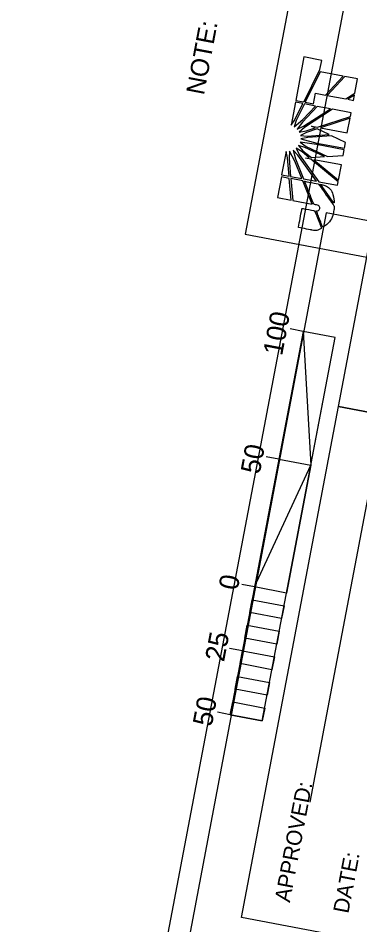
# Model space of a CAD drawing. Extents: x 1615642 to 1617075, y 899305 to 901510.
# Drawn here: x 1616717.4 to 1616848.8, y 900421.5 to 900770.1 of the extents above; entities that cross this region are included whole.
import ezdxf

# ---------------------------------------------------------------- set-up
doc = ezdxf.new("R2010")
doc.units = 0
for name, color, linetype in [('Default', 7, 'Continuous'), ('DEV BORDER CELL', 7, 'Continuous'), ('Prop DSN Text', 7, 'Continuous'), ('Scratch_Level_0', 7, 'Continuous'), ('Sheet Clip Boundary CELL', 7, 'Continuous'), ('Sheet Data Field CELL', 7, 'Continuous'), ('Sheet Plan CELL', 7, 'Continuous'), ('Sheet Title CELL', 7, 'Continuous')]:
    doc.layers.add(name, color=color, linetype=linetype)

msp = doc.modelspace()

# ---------------------------------------------------------------- linework, layer by layer
at = {"layer": 'Default'}
for p, q in [((1616827.31, 900755.17), (1616824.15, 900738.45)), ((1616834.16, 900753.88), (1616827.31, 900755.17)), ((1616833.49, 900750.32), (1616834.16, 900753.88)), ((1616827.31, 900737.85), (1616833.49, 900750.32)), ((1616833.63, 900749.42), (1616827.78, 900737.76)), ((1616842.41, 900747.76), (1616833.63, 900749.42)), ((1616835.63, 900740.51), (1616842.41, 900747.76)), ((1616843.03, 900747.65), (1616836.29, 900740.38)), ((1616847.97, 900746.71), (1616843.03, 900747.65)), ((1616846.95, 900741.32), (1616847.97, 900746.71)), ((1616831.04, 900737.15), (1616831.81, 900741.23)), ((1616831.81, 900741.23), (1616835.63, 900740.51)), ((1616836.29, 900740.38), (1616843.4, 900739.04)), ((1616843.4, 900739.04), (1616846.95, 900741.32)), ((1616846.8, 900740.53), (1616844.18, 900738.89)), ((1616844.18, 900738.89), (1616846.41, 900738.47)), ((1616846.41, 900738.47), (1616846.8, 900740.53)), ((1616824.07, 900737.82), (1616822.36, 900729.01)), ((1616823.84, 900731.04), (1616826.93, 900737.28)), ((1616826.93, 900737.28), (1616824.07, 900737.82)), ((1616824.15, 900738.45), (1616827.22, 900737.87)), ((1616827.54, 900737.17), (1616824.37, 900730.71)), ((1616832.45, 900736.19), (1616826.81, 900730.17)), ((1616826.95, 900731.13), (1616831.74, 900736.32)), ((1616827.18, 900728.51), (1616837.54, 900735.22)), ((1616827.22, 900737.87), (1616827.31, 900737.85)), ((1616831.74, 900736.32), (1616827.54, 900737.17)), ((1616827.78, 900737.76), (1616827.84, 900737.75)), ((1616827.84, 900737.75), (1616831.04, 900737.15)), ((1616837.54, 900735.22), (1616832.45, 900736.19)), ((1616838.37, 900735.07), (1616827.5, 900728.08)), ((1616832.52, 900728.14), (1616845.25, 900732.31)), ((1616845.51, 900733.72), (1616838.37, 900735.07)), ((1616845.25, 900732.31), (1616845.51, 900733.72)), ((1616822.36, 900729.01), (1616823.84, 900731.04)), ((1616823.59, 900728.31), (1616826.95, 900731.13)), ((1616824.37, 900730.71), (1616823.59, 900728.31)), ((1616826.81, 900730.17), (1616824.69, 900727.39)), ((1616824.69, 900727.39), (1616827.18, 900728.51)), ((1616831.69, 900727.87), (1616830.19, 900728.58)), ((1616830.19, 900728.58), (1616832.52, 900728.14)), ((1616845.08, 900731.66), (1616833.66, 900727.92)), ((1616844.01, 900725.97), (1616845.08, 900731.66)), ((1616827.5, 900728.08), (1616825.48, 900726.27)), ((1616825.48, 900726.27), (1616828.21, 900726.76)), ((1616828.28, 900726.16), (1616825.97, 900725.01)), ((1616825.97, 900725.01), (1616828.57, 900724.79)), ((1616828.21, 900726.76), (1616831.69, 900727.87)), ((1616832.4, 900727.52), (1616828.28, 900726.16)), ((1616828.57, 900724.79), (1616836.99, 900725.33)), ((1616837.99, 900724.87), (1616828.83, 900724.24)), ((1616836.99, 900725.33), (1616832.4, 900727.52)), ((1616833.66, 900727.92), (1616844.01, 900725.97)), ((1616843.31, 900722.28), (1616837.99, 900724.87)), ((1616832.18, 900721.51), (1616825.84, 900722.36)), ((1616825.84, 900722.36), (1616828.18, 900720.79)), ((1616828.83, 900724.24), (1616826.09, 900723.67)), ((1616826.09, 900723.67), (1616832.28, 900722.08)), ((1616842.79, 900719.51), (1616832.18, 900721.51)), ((1616832.28, 900722.08), (1616842.89, 900720.07)), ((1616842.89, 900720.07), (1616843.31, 900722.28)), ((1616820.45, 900718.87), (1616818.76, 900709.92)), ((1616821.03, 900716.4), (1616820.45, 900718.87)), ((1616821.82, 900718.94), (1616821.64, 900716.28)), ((1616823.88, 900715.14), (1616821.82, 900718.94)), ((1616825.04, 900717.42), (1616823.18, 900719.36)), ((1616823.18, 900719.36), (1616824.14, 900716.04)), ((1616824.31, 900720.1), (1616825.54, 900717.68)), ((1616826.67, 900718.65), (1616824.31, 900720.1)), ((1616825.24, 900721.11), (1616826.96, 900719.15)), ((1616827.65, 900720.42), (1616825.24, 900721.11)), ((1616829.39, 900716.41), (1616826.67, 900718.65)), ((1616826.96, 900719.15), (1616830.18, 900716.49)), ((1616835.2, 900716.86), (1616827.65, 900720.42)), ((1616828.18, 900720.79), (1616836.35, 900716.92)), ((1616842.37, 900717.33), (1616842.79, 900719.51)), ((1616821.61, 900709.38), (1616821.03, 900716.4)), ((1616821.64, 900716.28), (1616822.22, 900709.27)), ((1616826.53, 900708.45), (1616823.88, 900715.14)), ((1616824.14, 900716.04), (1616827.22, 900708.32)), ((1616832.19, 900707.38), (1616825.04, 900717.42)), ((1616825.54, 900717.68), (1616833.03, 900707.22)), ((1616827.87, 900716.29), (1616829.39, 900716.41)), ((1616829.97, 900715.89), (1616827.87, 900716.29)), ((1616840.5, 900707.17), (1616829.97, 900715.89)), ((1616830.18, 900716.49), (1616835.2, 900716.86)), ((1616841.73, 900713.72), (1616831.12, 900715.68)), ((1616831.12, 900715.68), (1616840.61, 900707.79)), ((1616836.35, 900716.92), (1616842.37, 900717.33)), ((1616840.61, 900707.79), (1616841.73, 900713.72)), ((1616818.64, 900709.09), (1616817.14, 900701.13)), ((1616821.71, 900708.51), (1616818.64, 900709.09)), ((1616818.76, 900709.92), (1616821.61, 900709.38)), ((1616822.41, 900700.13), (1616821.71, 900708.51)), ((1616822.22, 900709.27), (1616826.53, 900708.45)), ((1616826.9, 900707.53), (1616822.29, 900708.4)), ((1616822.29, 900708.4), (1616823.02, 900700.02)), ((1616830.44, 900698.62), (1616826.9, 900707.53)), ((1616827.22, 900708.32), (1616832.19, 900707.38)), ((1616833.03, 900707.22), (1616840.25, 900705.86)), ((1616840.25, 900705.86), (1616840.5, 900707.17)), ((1616817.14, 900701.13), (1616822.41, 900700.13)), ((1616823.02, 900700.02), (1616830.44, 900698.62))]:
    msp.add_line(p, q, dxfattribs=at)
for points in [[(1616827.78, 900737.76), (1616827.84, 900737.75), (1616831.04, 900737.15), (1616831.81, 900741.23), (1616835.63, 900740.51), (1616842.41, 900747.76), (1616833.63, 900749.42), (1616827.78, 900737.76)], [(1616836.29, 900740.38), (1616843.4, 900739.04), (1616846.95, 900741.32), (1616847.97, 900746.71), (1616843.03, 900747.65), (1616836.29, 900740.38), (1616836.29, 900740.38)], [(1616846.41, 900738.47), (1616846.41, 900738.47), (1616846.8, 900740.53), (1616844.18, 900738.89), (1616846.41, 900738.47)], [(1616823.84, 900731.04), (1616826.93, 900737.28), (1616824.07, 900737.82), (1616822.36, 900729.01), (1616823.84, 900731.04)], [(1616823.59, 900728.31), (1616826.95, 900731.13), (1616831.74, 900736.32), (1616827.54, 900737.17), (1616824.37, 900730.71), (1616823.59, 900728.31)], [(1616824.69, 900727.39), (1616827.18, 900728.51), (1616837.54, 900735.22), (1616832.45, 900736.19), (1616826.81, 900730.17), (1616824.69, 900727.39)], [(1616825.48, 900726.27), (1616828.21, 900726.76), (1616831.69, 900727.87), (1616830.19, 900728.58), (1616832.52, 900728.14), (1616845.25, 900732.31), (1616845.51, 900733.72), (1616838.37, 900735.07), (1616827.5, 900728.08), (1616825.48, 900726.27)], [(1616844.01, 900725.97), (1616845.08, 900731.66), (1616833.66, 900727.92), (1616844.01, 900725.97)], [(1616825.97, 900725.01), (1616828.57, 900724.79), (1616836.99, 900725.33), (1616832.4, 900727.52), (1616828.28, 900726.16), (1616825.97, 900725.01)], [(1616826.09, 900723.67), (1616832.28, 900722.08), (1616842.89, 900720.07), (1616843.31, 900722.28), (1616837.99, 900724.87), (1616828.83, 900724.24), (1616826.09, 900723.67)], [(1616828.18, 900720.79), (1616836.35, 900716.92), (1616842.37, 900717.33), (1616842.79, 900719.51), (1616832.18, 900721.51), (1616825.84, 900722.36), (1616828.18, 900720.79)], [(1616821.03, 900716.4), (1616820.45, 900718.87), (1616818.76, 900709.92), (1616821.61, 900709.38), (1616821.03, 900716.4)], [(1616822.22, 900709.27), (1616826.53, 900708.45), (1616823.88, 900715.14), (1616821.82, 900718.94), (1616821.64, 900716.28), (1616822.22, 900709.27)], [(1616827.22, 900708.32), (1616832.19, 900707.38), (1616825.04, 900717.42), (1616823.18, 900719.36), (1616824.14, 900716.04), (1616827.22, 900708.32)], [(1616824.31, 900720.1), (1616825.54, 900717.68), (1616833.03, 900707.22), (1616840.25, 900705.86), (1616840.5, 900707.17), (1616829.97, 900715.89), (1616827.87, 900716.29), (1616829.39, 900716.41), (1616826.67, 900718.65), (1616824.31, 900720.1)], [(1616825.24, 900721.11), (1616826.96, 900719.15), (1616830.18, 900716.49), (1616835.2, 900716.86), (1616827.65, 900720.42), (1616825.24, 900721.11)], [(1616840.61, 900707.79), (1616841.73, 900713.72), (1616831.12, 900715.68), (1616840.61, 900707.79)], [(1616822.41, 900700.13), (1616821.71, 900708.51), (1616818.64, 900709.09), (1616817.14, 900701.13), (1616822.41, 900700.13)], [(1616830.44, 900698.62), (1616826.9, 900707.53), (1616822.29, 900708.4), (1616823.02, 900700.02), (1616830.44, 900698.62)]]:
    msp.add_lwpolyline(points, dxfattribs=at)
for points in [[(1616833.44, 900696.87), (1616833.35, 900696.4), (1616833.01, 900696.04), (1616832.1, 900696.03), (1616832.1, 900696.03), (1616834.55, 900689.66), (1616834.55, 900689.66), (1616836.73, 900691.07), (1616838.37, 900693.67), (1616838.81, 900696.04), (1616838.93, 900696.66), (1616838.97, 900697.14), (1616838.96, 900697.82), (1616838.96, 900697.82), (1616832.91, 900706.39), (1616832.91, 900706.39), (1616832.91, 900706.39), (1616827.55, 900707.4), (1616827.55, 900707.4), (1616827.55, 900707.4), (1616831.11, 900698.49), (1616831.11, 900698.49), (1616833.11, 900698.11), (1616833.56, 900697.52), (1616833.44, 900696.87)], [(1616833.44, 900696.87), (1616833.35, 900696.4), (1616833.01, 900696.04), (1616832.1, 900696.03), (1616832.1, 900696.03), (1616834.55, 900689.66), (1616834.55, 900689.66), (1616836.73, 900691.07), (1616838.37, 900693.67), (1616838.81, 900696.04), (1616838.93, 900696.66), (1616838.97, 900697.14), (1616838.96, 900697.82), (1616838.96, 900697.82), (1616832.91, 900706.39), (1616832.91, 900706.39), (1616832.91, 900706.39), (1616827.55, 900707.4), (1616827.55, 900707.4), (1616827.55, 900707.4), (1616831.11, 900698.49), (1616831.11, 900698.49), (1616833.11, 900698.11), (1616833.56, 900697.52), (1616833.44, 900696.87)], [(1616833.75, 900706.23), (1616833.75, 900706.23), (1616838.97, 900698.83), (1616838.97, 900698.83), (1616838.8, 900702), (1616837.36, 900705.4), (1616833.75, 900706.23)], [(1616833.75, 900706.23), (1616833.75, 900706.23), (1616838.97, 900698.83), (1616838.97, 900698.83), (1616838.8, 900702), (1616837.36, 900705.4), (1616833.75, 900706.23)], [(1616826.59, 900696.98), (1616826.59, 900696.98), (1616825.2, 900689.61), (1616825.2, 900689.61), (1616825.2, 900689.61), (1616829.81, 900688.74), (1616829.81, 900688.74), (1616829.81, 900688.74), (1616830.29, 900688.65), (1616830.29, 900688.65), (1616831.74, 900688.38), (1616832.97, 900688.64), (1616834.09, 900689.29), (1616834.09, 900689.29), (1616831.55, 900696.04), (1616831.46, 900696.06), (1616831.46, 900696.06), (1616826.59, 900696.98), (1616826.59, 900696.98)], [(1616826.59, 900696.98), (1616826.59, 900696.98), (1616825.2, 900689.61), (1616825.2, 900689.61), (1616825.2, 900689.61), (1616829.81, 900688.74), (1616829.81, 900688.74), (1616829.81, 900688.74), (1616830.29, 900688.65), (1616830.29, 900688.65), (1616831.74, 900688.38), (1616832.97, 900688.64), (1616834.09, 900689.29), (1616834.09, 900689.29), (1616831.55, 900696.04), (1616831.46, 900696.06), (1616831.46, 900696.06), (1616826.59, 900696.98), (1616826.59, 900696.98)]]:
    msp.add_open_spline(points, degree=3, dxfattribs=at)
at = {"layer": 'DEV BORDER CELL'}
msp.add_line((1616829.71, 900468.75), (1616857, 900612.52), dxfattribs=at)
for points in [[(1616840.59, 900620.87), (1616861.86, 900732.87), (1616996.95, 900707.23), (1616975.68, 900595.22)], [(1616803.28, 900424.35), (1616840.59, 900620.87), (1616975.68, 900595.22), (1616938.37, 900398.7)]]:
    msp.add_lwpolyline(points, close=True, dxfattribs=at)
at = {"layer": 'Scratch_Level_0'}
msp.add_lwpolyline([(1616054.34, 901080.76), (1615793.19, 899705.33), (1616726.52, 899528.12), (1616890.46, 900391.55), (1616774.26, 900413.61), (1616871.48, 900925.61)], close=True, dxfattribs=at)
at = {"layer": 'Sheet Clip Boundary CELL'}
msp.add_lwpolyline([(1616176.29, 901060.7), (1616913.78, 900900.04), (1616896.28, 900812.91), (1616872.94, 900688.21), (1616835.87, 900695.21), (1616753.94, 900262.18), (1616898.09, 900233.43), (1616663.91, 899565.73), (1616252.62, 899604.04), (1615894.68, 899796.73), (1615981.58, 900932.46), (1616145.94, 900899.57)], close=True, dxfattribs=at)
at = {"layer": 'Sheet Data Field CELL'}
for p, q in [((1616826.99, 900649.7), (1616822.06, 900650.64)), ((1616817.65, 900600.58), (1616812.75, 900601.51)), ((1616803.68, 900526.9), (1616798.77, 900527.83)), ((1616799.01, 900502.34), (1616794.11, 900503.27))]:
    msp.add_line(p, q, dxfattribs=at)
at = {"layer": 'Sheet Plan CELL'}
msp.add_lwpolyline([(1616859.19, 900973.59), (1616804.79, 900687.04), (1616851.47, 900678.18), (1616905.88, 900964.73)], close=True, dxfattribs=at)
at = {"layer": 'Sheet Title CELL'}
for p, q in [((1616826.98, 900649.69), (1616799.02, 900502.32)), ((1616826.98, 900649.69), (1616822.07, 900650.62)), ((1616839.28, 900647.36), (1616826.98, 900649.69)), ((1616811.3, 900499.99), (1616839.28, 900647.36)), ((1616817.66, 900600.57), (1616812.76, 900601.5)), ((1616817.66, 900600.57), (1616829.94, 900598.24)), ((1616808.35, 900551.44), (1616803.44, 900552.37)), ((1616805.54, 900536.71), (1616817.82, 900534.38)), ((1616803.69, 900526.88), (1616798.76, 900527.82)), ((1616799.02, 900502.32), (1616794.12, 900503.25)), ((1616799.02, 900502.32), (1616811.3, 900499.99))]:
    msp.add_line(p, q, dxfattribs=at)
for points in [[(1616826.98, 900649.69), (1616829.94, 900598.24), (1616839.28, 900647.36)], [(1616808.35, 900551.44), (1616829.94, 900598.24), (1616820.63, 900549.11)], [(1616806.47, 900541.62), (1616807.41, 900546.53), (1616819.7, 900544.2), (1616818.75, 900539.29)], [(1616804.62, 900531.79), (1616805.54, 900536.71), (1616817.82, 900534.38), (1616816.89, 900529.46)], [(1616802.76, 900521.97), (1616803.69, 900526.88), (1616815.96, 900524.55), (1616815.03, 900519.64)], [(1616800.88, 900512.15), (1616801.82, 900517.06), (1616814.11, 900514.73), (1616813.18, 900509.83)], [(1616799.02, 900502.32), (1616799.95, 900507.23), (1616812.23, 900504.9), (1616811.3, 900499.99)]]:
    msp.add_lwpolyline(points, close=True, dxfattribs=at)

# ---------------------------------------------------------------- texts
at = {"layer": 'DEV BORDER CELL'}
for s, p in [('APPROVED:  ', (1616821.9, 900429.94)), ('DATE:  ', (1616844.4, 900425.67))]:
    msp.add_text(s, height=6, rotation=79.2494, dxfattribs=at).set_placement(p)
at = {"layer": 'Prop DSN Text'}
msp.add_text('NOTE: ', height=7, rotation=79.2494, dxfattribs=at).set_placement((1616788.86, 900740.27))
at = {"layer": 'Sheet Title CELL'}
for s, p in [('100', (1616818.91, 900640.06)), ('50', (1616810.27, 900594.53)), ('0', (1616801.8, 900549.89)), ('25', (1616796.58, 900522.4)), ('50', (1616791.85, 900497.5))]:
    msp.add_text(s, height=7.5, rotation=79.2541, dxfattribs=at).set_placement(p)

doc.saveas('drawing.dxf')
